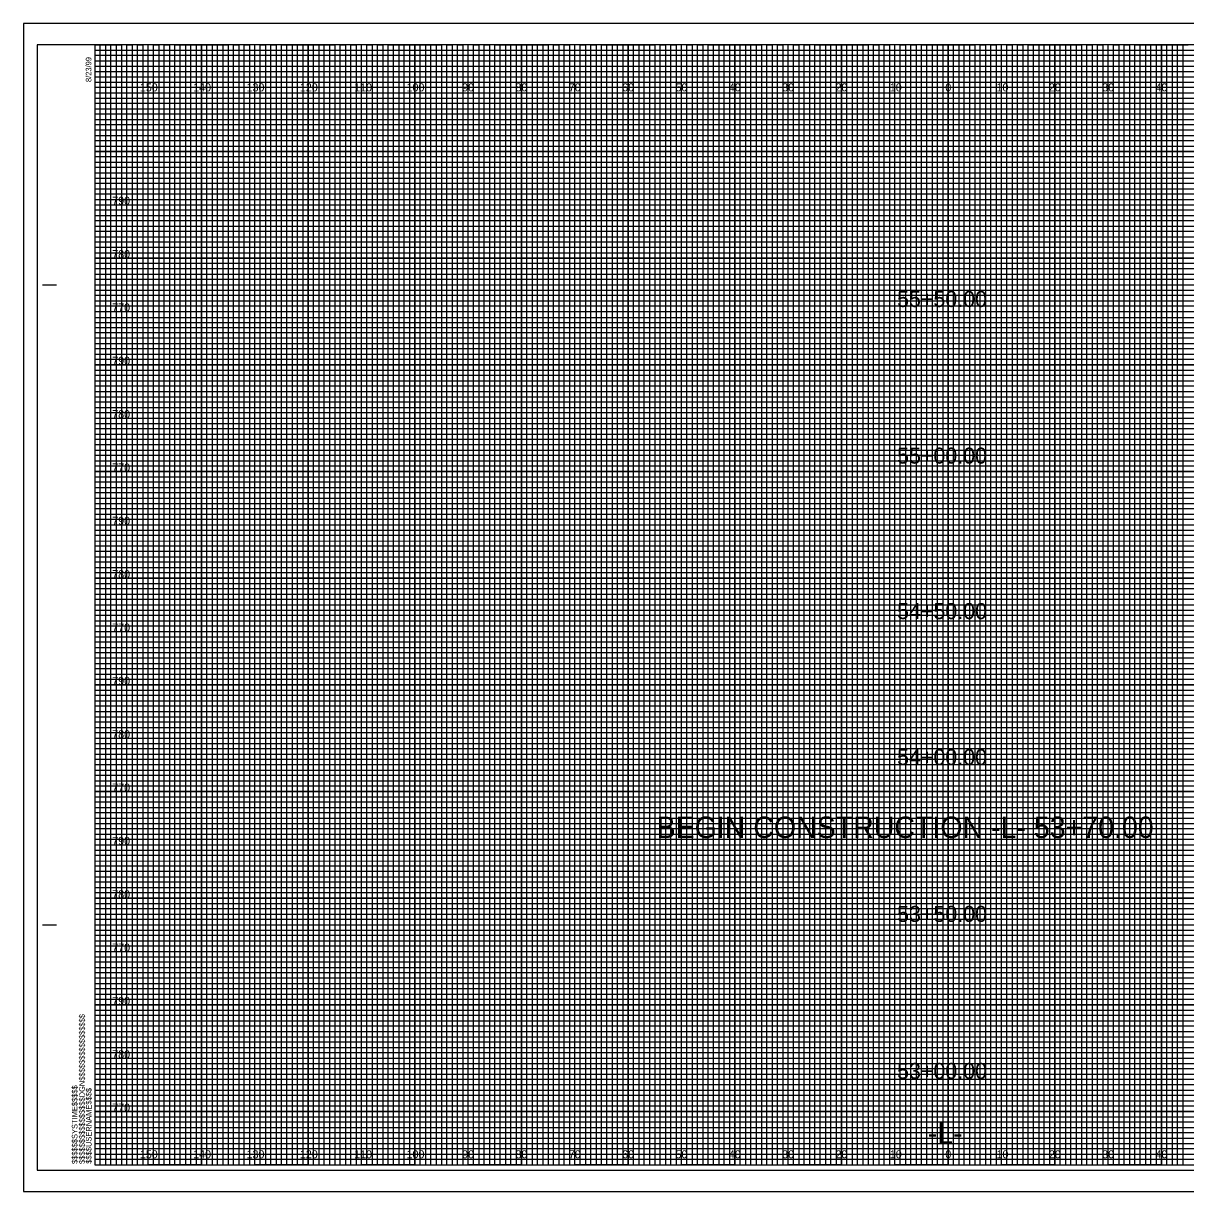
# Model space of a CAD drawing. Extents: x -13 to 398, y -5 to 214.
# Drawn here: x -13.4 to 204.5, y -5 to 214 of the extents above; entities that cross this region are included whole.
import ezdxf

# ---------------------------------------------------------------- set-up
doc = ezdxf.new("R2010")
doc.units = 0
for name, color, linetype in [('Exist Cross Section Cell', 7, 'Continuous'), ('Exist XS Center Line Elevation Label', 7, 'Continuous'), ('Exist XS Ground Line', 7, 'Continuous'), ('Prop XS Ditch Slope Text', 7, 'Continuous'), ('Prop XS Ditch Standard Text', 7, 'Continuous'), ('Prop XS Dump Level', 7, 'Continuous'), ('Prop XS EOT Tick Mark', 7, 'Continuous'), ('Prop XS Finish Grade', 7, 'Continuous'), ('Prop XS Finish Grade Paved Shoulder', 7, 'Continuous'), ('Prop XS Finish Grade Pavement', 7, 'Continuous'), ('Prop XS Pvmt Edge Slope', 7, 'Continuous'), ('Prop XS Side Slope Text', 7, 'Continuous'), ('Prop XS Subgrade Earthwork', 7, 'Continuous')]:
    doc.layers.add(name, color=color, linetype=linetype)

msp = doc.modelspace()

# ---------------------------------------------------------------- linework, layer by layer
at = {"layer": 'Exist XS Center Line Elevation Label'}
for points in [[(0, 210), (5, 210), (5, 0), (15, 0), (15, 210), (25, 210), (25, 0), (35, 0), (35, 210), (45, 210), (45, 0), (55, 0), (55, 210), (65, 210), (65, 0), (75, 0), (75, 210), (85, 210), (85, 0), (95, 0), (95, 210), (105, 210), (105, 0), (115, 0), (115, 210), (125, 210), (125, 0), (135, 0), (135, 210), (145, 210), (145, 0), (155, 0), (155, 210), (165, 210), (165, 0), (175, 0), (175, 210), (185, 210), (185, 0), (195, 0), (195, 210), (205, 210)], [(0, 205), (275, 205)], [(0, 185), (320, 185), (320, 195), (0, 195)], [(0, 165), (320, 165), (320, 175), (0, 175)], [(0, 145), (320, 145), (320, 155), (0, 155)], [(0, 125), (320, 125), (320, 135), (0, 135)], [(0, 105), (320, 105), (320, 115), (0, 115)], [(0, 85), (320, 85), (320, 95), (0, 95)], [(0, 65), (320, 65), (320, 75), (0, 75)], [(0, 45), (320, 45), (320, 55), (0, 55)], [(0, 25), (320, 25), (320, 35), (0, 35)], [(0, 5), (320, 5), (320, 15), (0, 15)]]:
    msp.add_lwpolyline(points, dxfattribs=at)
at = {"layer": 'Exist XS Ground Line'}
for p, q in [((10, 210), (0, 210)), ((10, 0), (10, 210)), ((30, 210), (20, 210)), ((20, 210), (20, 0)), ((30, 0), (30, 210)), ((50, 210), (40, 210)), ((40, 210), (40, 0)), ((50, 0), (50, 210)), ((70, 210), (60, 210)), ((60, 210), (60, 0)), ((70, 0), (70, 210)), ((90, 210), (80, 210)), ((80, 210), (80, 0)), ((90, 0), (90, 210)), ((110, 210), (100, 210)), ((100, 210), (100, 0)), ((110, 0), (110, 210)), ((130, 210), (120, 210)), ((120, 210), (120, 0)), ((130, 0), (130, 210)), ((150, 210), (140, 210)), ((140, 210), (140, 0)), ((150, 0), (150, 210)), ((170, 210), (160, 210)), ((160, 210), (160, 0)), ((170, 0), (170, 210)), ((190, 210), (180, 210)), ((180, 210), (180, 0)), ((190, 0), (190, 210)), ((210, 210), (200, 210)), ((200, 210), (200, 0)), ((20, 0), (10, 0)), ((40, 0), (30, 0)), ((60, 0), (50, 0)), ((80, 0), (70, 0)), ((100, 0), (90, 0)), ((120, 0), (110, 0)), ((140, 0), (130, 0)), ((160, 0), (150, 0)), ((180, 0), (170, 0)), ((200, 0), (190, 0))]:
    msp.add_line(p, q, dxfattribs=at)
for points in [[(0, 200), (320, 200), (320, 190), (0, 190)], [(0, 180), (320, 180), (320, 170), (0, 170)], [(0, 160), (320, 160), (320, 150), (0, 150)], [(0, 140), (320, 140), (320, 130), (0, 130)], [(0, 120), (320, 120), (320, 110), (0, 110)], [(0, 100), (320, 100), (320, 90), (0, 90)], [(0, 80), (320, 80), (320, 70), (0, 70)], [(0, 60), (320, 60), (320, 50), (0, 50)], [(0, 40), (320, 40), (320, 30), (0, 30)], [(0, 20), (320, 20), (320, 10), (0, 10)]]:
    msp.add_lwpolyline(points, dxfattribs=at)
at = {"layer": 'Prop XS Ditch Slope Text'}
for points in [[(0, 0), (1, 0), (1, 210), (2, 210), (2, 0)], [(2, 0), (3, 0), (3, 210), (4, 210), (4, 0)], [(5, 0), (6, 0), (6, 210), (7, 210), (7, 0)], [(7, 0), (8, 0), (8, 210), (9, 210), (9, 0)], [(10, 0), (11, 0), (11, 210), (12, 210), (12, 0)], [(12, 0), (13, 0), (13, 210), (14, 210), (14, 0)], [(15, 0), (16, 0), (16, 210), (17, 210), (17, 0)], [(17, 0), (18, 0), (18, 210), (19, 210), (19, 0)], [(20, 0), (21, 0), (21, 210), (22, 210), (22, 0)], [(22, 0), (23, 0), (23, 210), (24, 210), (24, 0)], [(25, 0), (26, 0), (26, 210), (27, 210), (27, 0)], [(27, 0), (28, 0), (28, 210), (29, 210), (29, 0)], [(30, 0), (31, 0), (31, 210), (32, 210), (32, 0)], [(32, 0), (33, 0), (33, 210), (34, 210), (34, 0)], [(35, 0), (36, 0), (36, 210), (37, 210), (37, 0)], [(37, 0), (38, 0), (38, 210), (39, 210), (39, 0)], [(40, 0), (41, 0), (41, 210), (42, 210), (42, 0)], [(42, 0), (43, 0), (43, 210), (44, 210), (44, 0)], [(45, 0), (46, 0), (46, 210), (47, 210), (47, 0)], [(47, 0), (48, 0), (48, 210), (49, 210), (49, 0)], [(50, 0), (51, 0), (51, 210), (52, 210), (52, 0)], [(52, 0), (53, 0), (53, 210), (54, 210), (54, 0)], [(55, 0), (56, 0), (56, 210), (57, 210), (57, 0)], [(57, 0), (58, 0), (58, 210), (59, 210), (59, 0)], [(60, 0), (61, 0), (61, 210), (62, 210), (62, 0)], [(62, 0), (63, 0), (63, 210), (64, 210), (64, 0)], [(65, 0), (66, 0), (66, 210), (67, 210), (67, 0)], [(67, 0), (68, 0), (68, 210), (69, 210), (69, 0)], [(70, 0), (71, 0), (71, 210), (72, 210), (72, 0)], [(72, 0), (73, 0), (73, 210), (74, 210), (74, 0)], [(75, 0), (76, 0), (76, 210), (77, 210), (77, 0)], [(77, 0), (78, 0), (78, 210), (79, 210), (79, 0)], [(80, 0), (81, 0), (81, 210), (82, 210), (82, 0)], [(82, 0), (83, 0), (83, 210), (84, 210), (84, 0)], [(85, 0), (86, 0), (86, 210), (87, 210), (87, 0)], [(87, 0), (88, 0), (88, 210), (89, 210), (89, 0)], [(90, 0), (91, 0), (91, 210), (92, 210), (92, 0)], [(92, 0), (93, 0), (93, 210), (94, 210), (94, 0)], [(95, 0), (96, 0), (96, 210), (97, 210), (97, 0)], [(97, 0), (98, 0), (98, 210), (99, 210), (99, 0)], [(100, 0), (101, 0), (101, 210), (102, 210), (102, 0)], [(102, 0), (103, 0), (103, 210), (104, 210), (104, 0)], [(105, 0), (106, 0), (106, 210), (107, 210), (107, 0)], [(107, 0), (108, 0), (108, 210), (109, 210), (109, 0)], [(110, 0), (111, 0), (111, 210), (112, 210), (112, 0)], [(112, 0), (113, 0), (113, 210), (114, 210), (114, 0)], [(115, 0), (116, 0), (116, 210), (117, 210), (117, 0)], [(117, 0), (118, 0), (118, 210), (119, 210), (119, 0)], [(120, 0), (121, 0), (121, 210), (122, 210), (122, 0)], [(122, 0), (123, 0), (123, 210), (124, 210), (124, 0)], [(125, 0), (126, 0), (126, 210), (127, 210), (127, 0)], [(127, 0), (128, 0), (128, 210), (129, 210), (129, 0)], [(130, 0), (131, 0), (131, 210), (132, 210), (132, 0)], [(132, 0), (133, 0), (133, 210), (134, 210), (134, 0)], [(135, 0), (136, 0), (136, 210), (137, 210), (137, 0)], [(137, 0), (138, 0), (138, 210), (139, 210), (139, 0)], [(140, 0), (141, 0), (141, 210), (142, 210), (142, 0)], [(142, 0), (143, 0), (143, 210), (144, 210), (144, 0)], [(145, 0), (146, 0), (146, 210), (147, 210), (147, 0)], [(147, 0), (148, 0), (148, 210), (149, 210), (149, 0)], [(150, 0), (151, 0), (151, 210), (152, 210), (152, 0)], [(152, 0), (153, 0), (153, 210), (154, 210), (154, 0)], [(155, 0), (156, 0), (156, 210), (157, 210), (157, 0)], [(157, 0), (158, 0), (158, 210), (159, 210), (159, 0)], [(160, 0), (161, 0), (161, 210), (162, 210), (162, 0)], [(162, 0), (163, 0), (163, 210), (164, 210), (164, 0)], [(165, 0), (166, 0), (166, 210), (167, 210), (167, 0)], [(167, 0), (168, 0), (168, 210), (169, 210), (169, 0)], [(170, 0), (171, 0), (171, 210), (172, 210), (172, 0)], [(172, 0), (173, 0), (173, 210), (174, 210), (174, 0)], [(175, 0), (176, 0), (176, 210), (177, 210), (177, 0)], [(177, 0), (178, 0), (178, 210), (179, 210), (179, 0)], [(180, 0), (181, 0), (181, 210), (182, 210), (182, 0)], [(182, 0), (183, 0), (183, 210), (184, 210), (184, 0)], [(185, 0), (186, 0), (186, 210), (187, 210), (187, 0)], [(187, 0), (188, 0), (188, 210), (189, 210), (189, 0)], [(190, 0), (191, 0), (191, 210), (192, 210), (192, 0)], [(192, 0), (193, 0), (193, 210), (194, 210), (194, 0)], [(195, 0), (196, 0), (196, 210), (197, 210), (197, 0)], [(197, 0), (198, 0), (198, 210), (199, 210), (199, 0)], [(200, 0), (201, 0), (201, 210), (202, 210), (202, 0)], [(202, 0), (203, 0), (203, 210), (204, 210), (204, 0)]]:
    msp.add_lwpolyline(points, dxfattribs=at)
at = {"layer": 'Prop XS Ditch Standard Text'}
for p, q in [((-9.8, 165), (-7.3, 165)), ((-9.7, 165), (-7.2, 165)), ((-9.8, 45), (-7.3, 45)), ((-9.7, 45), (-7.2, 45)), ((0, 0), (0, 0)), ((0, 0), (0, 0)), ((0, 0), (0, 0)), ((0, 0), (0, 0)), ((0, 0), (0, 0)), ((0, 0), (0, 0)), ((0, 0), (0, 0))]:
    msp.add_line(p, q, dxfattribs=at)
msp.add_lwpolyline([(320, 210), (0, 210), (0, 0), (320, 0)], close=True, dxfattribs=at)
at = {"layer": 'Prop XS Dump Level'}
for p, q in [((0, 209), (260, 209)), ((260, 207.98), (0, 207.98)), ((0, 207.98), (0, 207)), ((0, 207), (260, 207)), ((260, 205.89), (0, 205.89)), ((0, 205.89), (0, 204)), ((0, 204), (320, 204))]:
    msp.add_line(p, q, dxfattribs=at)
for points in [[(0, 203), (270, 203), (320, 203), (320, 202), (0, 202)], [(0, 201), (320, 201), (320, 199), (0, 199)], [(0, 198), (320, 198), (320, 197), (0, 196.98)], [(0, 196), (320, 196), (320, 194), (0, 194)], [(0, 193), (320, 193), (320, 192), (0, 192)], [(0, 191), (320, 191), (320, 189), (0, 189)], [(0, 188), (320, 188), (320, 187), (0, 187)], [(0, 186), (320, 186), (320, 184), (0, 184)], [(0, 183), (320, 183), (320, 182), (0, 182)], [(0, 181), (320, 181), (320, 179), (0, 179)], [(0, 178), (320, 178), (320, 177), (0, 177)], [(0, 176), (320, 176), (320, 173.95), (320, 173), (320, 172), (0, 172)], [(0, 174), (320, 174), (320, 173), (0, 173)], [(0, 171), (320, 171), (320, 169), (0, 169.03)], [(0, 169.03), (320, 169), (320, 168), (0, 168)], [(0, 167), (320, 167), (320, 166), (0, 166)], [(0, 164), (320, 164), (320, 163), (0, 163)], [(0, 162), (320, 162), (320, 161), (0, 161)], [(-0.07, 158.89), (320, 158.89), (320, 157.88), (-0.07, 157.88)], [(0, 157), (320, 157), (320, 156), (0, 156)], [(0, 154), (320, 154), (320, 153), (0, 153)], [(0, 152), (320, 152), (320, 151), (0, 151)], [(0, 149), (320, 149), (320, 148), (0, 148)], [(0, 147), (320, 147), (320, 146), (0, 146)], [(0, 144), (320, 144), (320, 143), (0, 143)], [(0, 142), (320, 142), (320, 141), (0, 141)], [(0, 139), (320, 139), (319.99, 137.98), (0, 138)], [(0, 137), (320, 137), (320, 136), (0, 136)], [(0, 134), (320, 134), (320, 133), (0, 133)], [(0, 132), (320, 132), (320, 131), (0, 131)], [(0, 129), (320, 129), (320, 128), (0, 128)], [(0, 127), (320, 127), (320, 126), (0, 126)], [(0, 124), (320, 124), (320, 123), (0, 123)], [(0, 122), (320, 122), (320, 121), (0, 121)], [(0, 119), (320, 119), (320, 118), (0, 118)], [(0, 116.99), (320.07, 116.91), (320, 116), (0, 116)], [(0, 114), (320, 114), (320, 113), (0, 113)], [(0, 112), (320, 112), (320, 111), (0, 111)], [(0, 109), (320, 109), (320, 108), (0, 108)], [(0, 107), (320, 107), (320, 106), (0, 106)], [(0, 104), (320, 104), (320, 103), (0, 103)], [(0, 102), (320, 102), (320, 101), (0, 101)], [(0, 99), (320, 99), (320, 98), (0, 98)], [(0, 97), (320, 97), (320, 96), (0, 96)], [(0, 94), (320, 94), (320, 93), (0, 93)], [(0, 92), (320, 92), (320, 91), (0, 91)], [(0, 89), (320, 89), (320, 88), (0, 88)], [(0, 87), (320, 87), (320, 86), (0, 86)], [(0, 84), (320, 84), (320, 83), (0, 83)], [(0, 82), (320, 82), (320, 81), (0, 81)], [(0, 79), (320, 79), (319.99, 77.98), (0, 78)], [(0, 77), (320, 77), (320, 76), (0, 76)], [(0, 74), (320, 74), (320, 73), (0, 73)], [(0, 72), (320, 72), (320, 71), (0, 71)], [(0, 69), (320, 69), (320, 68), (0, 68)], [(0, 67), (320, 67), (320, 66), (0, 66)], [(0, 64), (320, 64), (320, 63), (0, 63)], [(0, 62), (320, 62), (320, 61), (0, 61)], [(0, 59), (320, 59), (320, 58), (0, 58)], [(0, 56.99), (320.07, 56.91), (320, 56), (0, 56)], [(0, 54), (320, 54), (320, 53), (0, 53)], [(0, 52), (320, 52), (320, 51), (0, 51)], [(0, 49), (320, 49), (320, 48), (0, 48)], [(0, 47), (320, 47), (320, 46), (0, 46)], [(0, 44), (320, 44), (320, 43), (0, 43)], [(0, 42), (320, 42), (320, 41), (0, 41)], [(0, 39), (320, 39), (320, 38), (0, 38)], [(0, 37), (320, 37), (320, 36), (0, 36)], [(0, 34), (320, 34), (320, 33), (0, 33)], [(0, 32), (320, 32), (320, 31), (0, 31)], [(0, 29), (320, 29), (320, 28), (0, 28)], [(0, 27), (320, 27), (320, 26), (0, 26)], [(0, 24), (320, 24), (320, 23), (0, 23)], [(0, 22), (320, 22), (320, 21), (0, 21)], [(0, 19), (320, 19), (320, 18), (0, 18)], [(0, 17), (320, 17), (320, 16), (0, 16)], [(0, 14), (320, 14), (320, 13), (0, 13)], [(0, 12), (320, 12), (320, 11), (0, 11)], [(0, 9), (320, 9), (320, 8), (0, 8)], [(0, 7), (320, 7), (320, 6), (0, 6)], [(0, 4), (320, 4), (320, 3), (0, 3)], [(0, 2), (320, 2), (320, 1), (0, 1)]]:
    msp.add_lwpolyline(points, dxfattribs=at)
at = {"layer": 'Prop XS EOT Tick Mark'}
for p, q in [((10, 0), (10, 210)), ((20, 0), (20, 210)), ((30, 0), (30, 210)), ((40, 0), (40, 210)), ((50, 0), (50, 210)), ((60, 0), (60, 210)), ((70, 0), (70, 210)), ((80, 0), (80, 210)), ((90, 0), (90, 210)), ((100, 0), (100, 210)), ((110, 0), (110, 210)), ((120, 0), (120, 210)), ((130, 0), (130, 210)), ((140, 0), (140, 210)), ((150, 0), (150, 210)), ((160, 0), (160, 210)), ((170, 0), (170, 210)), ((180, 0), (180, 210)), ((190, 0), (190, 210)), ((200, 0), (200, 210)), ((0, 200), (320, 200)), ((0, 190), (320, 190)), ((0, 180), (320, 180)), ((0, 170), (320, 170)), ((0, 160), (320, 160)), ((0, 150), (320, 150)), ((0, 140), (320, 140)), ((0, 130), (320, 130)), ((0, 120), (320, 120)), ((0, 110), (320, 110)), ((0, 100), (320, 100)), ((0, 90), (320, 90)), ((0, 80), (320, 80)), ((0, 70), (320, 70)), ((0, 60), (320, 60)), ((0, 50), (320, 50)), ((0, 40), (320, 40)), ((0, 30), (320, 30)), ((0, 20), (320, 20)), ((0, 10), (320, 10))]:
    msp.add_line(p, q, dxfattribs=at)
at = {"layer": 'Prop XS Finish Grade Pavement'}
msp.add_lwpolyline([(-13.4, -5), (323.3, -5), (323.3, 214), (-13.4, 214)], close=True, dxfattribs=at)
at = {"layer": 'Prop XS Pvmt Edge Slope'}
for p, q in [((323.3, 214), (-13.4, 214)), ((-13.4, 214), (-13.4, -5)), ((-13.4, -5), (323.3, -5))]:
    msp.add_line(p, q, dxfattribs=at)
at = {"layer": 'Prop XS Subgrade Earthwork'}
msp.add_lwpolyline([(-10.8, -1), (322.4, -1), (322.4, 210), (-10.8, 210)], close=True, dxfattribs=at)

# ---------------------------------------------------------------- texts
at = {"layer": 'Exist Cross Section Cell'}
for s, p in [('150', (8.44, 201.25)), ('140', (18.44, 201.25)), ('130', (28.44, 201.25)), ('120', (38.44, 201.25)), ('110', (48.62, 201.25)), ('100', (58.44, 201.25)), ('90', (68.86, 201.25)), ('80', (78.86, 201.25)), ('70', (88.86, 201.25)), ('60', (98.86, 201.25)), ('50', (108.86, 201.25)), ('40', (118.86, 201.25)), ('30', (128.86, 201.25)), ('20', (138.86, 201.25)), ('10', (149.04, 201.25)), ('0', (159.45, 201.25)), ('0', (159.45, 201.25)), ('10', (169.04, 201.25)), ('20', (178.86, 201.25)), ('30', (188.86, 201.25)), ('40', (198.86, 201.25)), ('150', (8.44, 1.25)), ('140', (18.44, 1.25)), ('130', (28.44, 1.25)), ('120', (38.44, 1.25)), ('110', (48.62, 1.25)), ('100', (58.44, 1.25)), ('90', (68.86, 1.25)), ('80', (78.86, 1.25)), ('70', (88.86, 1.25)), ('60', (98.86, 1.25)), ('50', (108.86, 1.25)), ('40', (118.86, 1.25)), ('30', (128.86, 1.25)), ('20', (138.86, 1.25)), ('10', (149.04, 1.25)), ('0', (159.45, 1.25)), ('0', (159.45, 1.25)), ('10', (169.04, 1.25)), ('20', (178.86, 1.25)), ('30', (188.86, 1.25)), ('40', (198.86, 1.25))]:
    msp.add_text(s, height=1.5, dxfattribs=at).set_placement(p)
at = {"layer": 'Prop XS Ditch Standard Text'}
for s, p in [('8/23/99', (-0.65, 203)), ('$$$$$$$$$$$$$$$$DGN$$$$$$$$$$$$$$$$', (-1.88, 0.18)), ('$$$$$$SYSTIME$$$$$', (-3.26, 0.18)), ('$$$$USERNAME$$$$', (-0.62, 0.23))]:
    msp.add_text(s, height=1.05, rotation=90, dxfattribs=at).set_placement(p)
at = {"layer": 'Prop XS Finish Grade'}
for s, p in [('55+50.00', (150.41, 160.83)), ('55+00.00', (150.41, 131.47)), ('54+50.00', (150.41, 102.33)), ('54+00.00', (150.41, 74.96)), ('53+50.00', (150.41, 45.56)), ('53+00.00', (150.41, 16.12))]:
    msp.add_text(s, height=3, dxfattribs=at).set_placement(p)
at = {"layer": 'Prop XS Finish Grade Paved Shoulder'}
for s, p in [('790', (3.26, 180)), ('780', (3.26, 170)), ('770', (3.26, 160)), ('790', (3.26, 150)), ('780', (3.26, 140)), ('770', (3.26, 130)), ('790', (3.26, 120)), ('780', (3.26, 110)), ('770', (3.26, 100)), ('790', (3.26, 90)), ('780', (3.26, 80)), ('770', (3.26, 70)), ('790', (3.26, 60)), ('780', (3.26, 50)), ('770', (3.26, 40)), ('790', (3.26, 30)), ('780', (3.26, 20)), ('770', (3.26, 10))]:
    msp.add_text(s, height=1.5, dxfattribs=at).set_placement(p)
at = {"layer": 'Prop XS Side Slope Text'}
for s, p in [('BEGIN CONSTRUCTION -L- 53+70.00', (105.32, 61.3)), ('-L-', (156.15, 4))]:
    msp.add_text(s, height=4, dxfattribs=at).set_placement(p)

doc.saveas('drawing.dxf')
